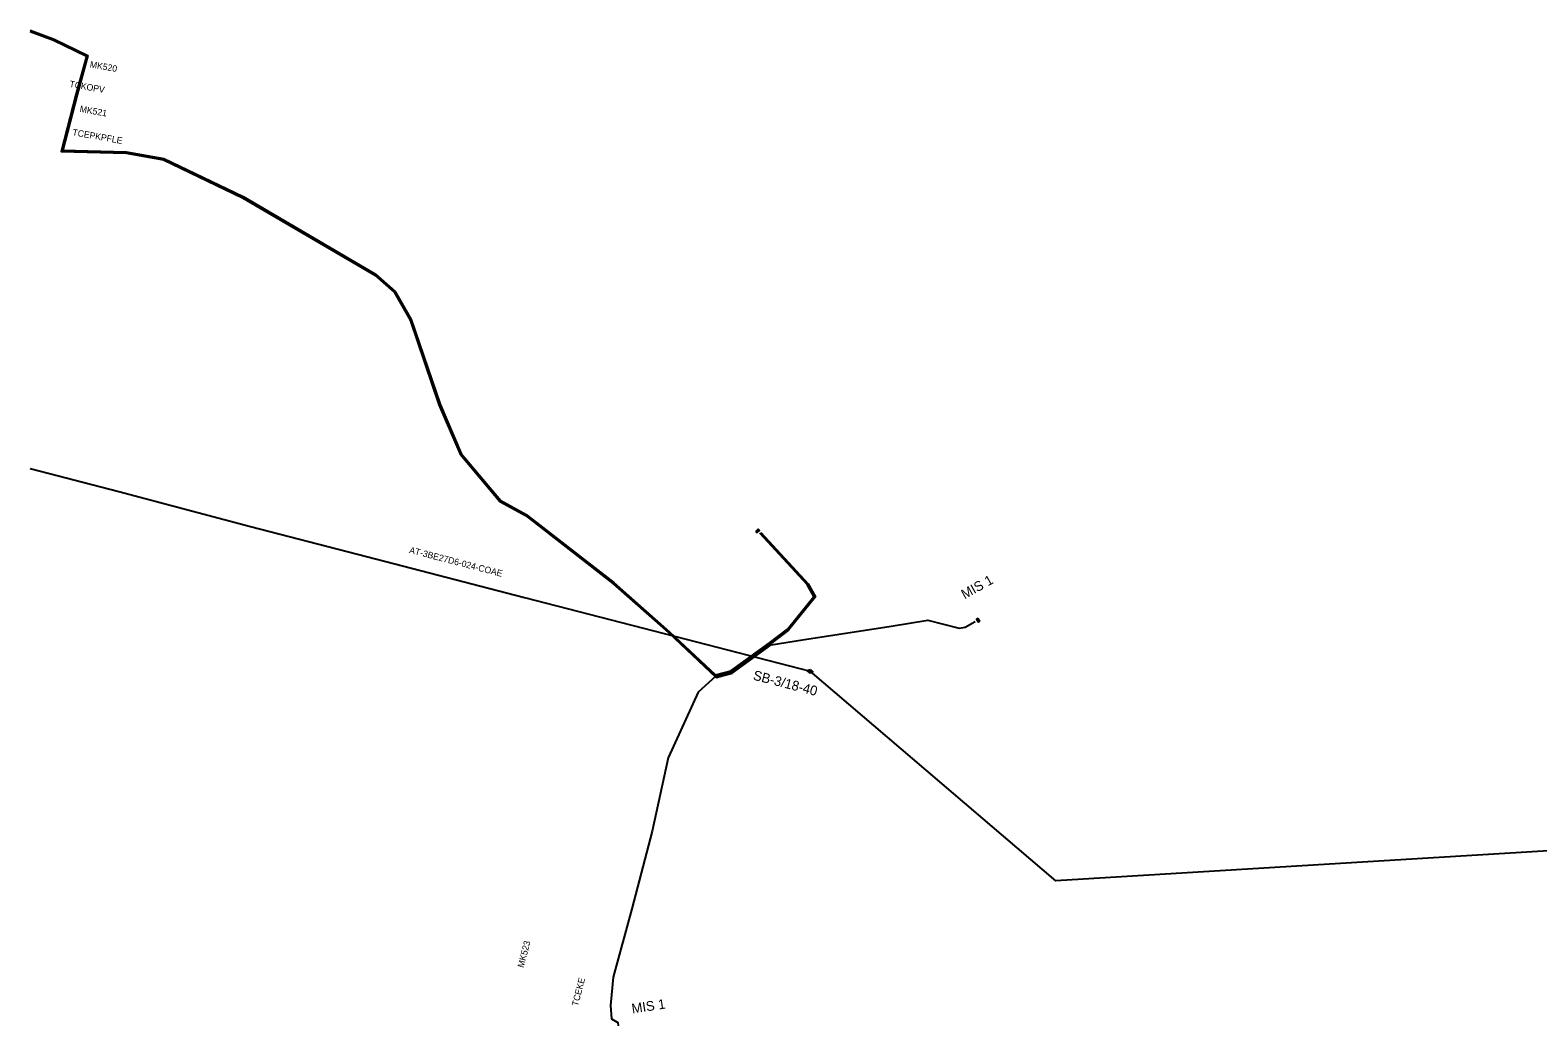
# Model space of a CAD drawing. Extents: x -762501 to -761573, y -1153000 to -1152000.
# Drawn here: x -762500 to -762268.5, y -1152869 to -1152715.9 of the extents above; entities that cross this region are included whole.
import ezdxf

# ---------------------------------------------------------------- set-up
doc = ezdxf.new("R2010")
doc.units = 0
for name, color, linetype in [('Vrstva 1', 7, 'Continuous'), ('Vrstva 10', 7, 'Continuous'), ('Vrstva 2', 7, 'Continuous'), ('Vrstva 9', 7, 'Continuous')]:
    doc.layers.add(name, color=color, linetype=linetype)

msp = doc.modelspace()

# ---------------------------------------------------------------- linework, layer by layer
at = {"layer": 'Vrstva 1'}
for points in [[(-762500, -1152783.22), (-762486.41, -1152786.73), (-762466.18, -1152792.12), (-762445.37, -1152797.51), (-762424.09, -1152803.02), (-762396.1, -1152810.24), (-762380.24, -1152814.37)], [(-761622.14, -1153000), (-761645.21, -1152899.52), (-761677.94, -1152853.03), (-761709.62, -1152807.98), (-762342.52, -1152846.53), (-762380.24, -1152814.37)], [(-762380.755, -1152814.237), (-762380.213, -1152814.113)], [(-762380.755, -1152814.237), (-762380.327, -1152814.604)], [(-762380.327, -1152814.604), (-762379.785, -1152814.479)], [(-762380.213, -1152814.113), (-762379.785, -1152814.479)]]:
    msp.add_lwpolyline(points, dxfattribs=at)
at = {"layer": 'Vrstva 9'}
for p, q in [((-762388.548, -1152792.888), (-762388.216, -1152792.579)), ((-762388.544, -1152792.892), (-762388.213, -1152792.583)), ((-762388.541, -1152792.895), (-762388.21, -1152792.586)), ((-762388.538, -1152792.899), (-762388.206, -1152792.59)), ((-762388.534, -1152792.903), (-762388.203, -1152792.594)), ((-762388.531, -1152792.906), (-762388.199, -1152792.597)), ((-762388.527, -1152792.91), (-762388.196, -1152792.601)), ((-762388.524, -1152792.914), (-762388.193, -1152792.605)), ((-762388.521, -1152792.917), (-762388.189, -1152792.608)), ((-762388.517, -1152792.921), (-762388.186, -1152792.612)), ((-762388.514, -1152792.924), (-762388.182, -1152792.616)), ((-762388.51, -1152792.928), (-762388.179, -1152792.619)), ((-762388.507, -1152792.932), (-762388.176, -1152792.623)), ((-762388.503, -1152792.935), (-762388.172, -1152792.626)), ((-762388.5, -1152792.939), (-762388.169, -1152792.63)), ((-762388.497, -1152792.943), (-762388.165, -1152792.634)), ((-762388.493, -1152792.946), (-762388.162, -1152792.637)), ((-762388.49, -1152792.95), (-762388.159, -1152792.641)), ((-762388.486, -1152792.954), (-762388.155, -1152792.645)), ((-762388.483, -1152792.957), (-762388.152, -1152792.648)), ((-762388.48, -1152792.961), (-762388.148, -1152792.652)), ((-762388.476, -1152792.965), (-762388.145, -1152792.656)), ((-762388.473, -1152792.968), (-762388.141, -1152792.659)), ((-762388.469, -1152792.972), (-762388.138, -1152792.663)), ((-762388.466, -1152792.976), (-762388.135, -1152792.667)), ((-762388.463, -1152792.979), (-762388.131, -1152792.67)), ((-762388.459, -1152792.983), (-762388.128, -1152792.674)), ((-762388.456, -1152792.987), (-762388.124, -1152792.678)), ((-762388.452, -1152792.99), (-762388.121, -1152792.681)), ((-762388.449, -1152792.994), (-762388.118, -1152792.685)), ((-762388.446, -1152792.998), (-762388.114, -1152792.689)), ((-762388.442, -1152793.001), (-762388.111, -1152792.692)), ((-762388.439, -1152793.005), (-762388.107, -1152792.696)), ((-762388.435, -1152793.009), (-762388.104, -1152792.7)), ((-762388.432, -1152793.012), (-762388.101, -1152792.703)), ((-762388.428, -1152793.016), (-762388.097, -1152792.707)), ((-762388.425, -1152793.02), (-762388.094, -1152792.711)), ((-762388.422, -1152793.023), (-762388.09, -1152792.714)), ((-762388.418, -1152793.027), (-762388.087, -1152792.718)), ((-762388.415, -1152793.031), (-762388.083, -1152792.722)), ((-762354.663, -1152806.355), (-762354.437, -1152806.748)), ((-762354.659, -1152806.353), (-762354.433, -1152806.745)), ((-762354.655, -1152806.35), (-762354.428, -1152806.743)), ((-762354.65, -1152806.348), (-762354.424, -1152806.74)), ((-762354.646, -1152806.345), (-762354.42, -1152806.738)), ((-762354.642, -1152806.343), (-762354.415, -1152806.735)), ((-762354.637, -1152806.34), (-762354.411, -1152806.733)), ((-762354.633, -1152806.338), (-762354.407, -1152806.73)), ((-762354.629, -1152806.335), (-762354.402, -1152806.728)), ((-762354.624, -1152806.333), (-762354.398, -1152806.725)), ((-762354.62, -1152806.33), (-762354.394, -1152806.723)), ((-762354.616, -1152806.328), (-762354.389, -1152806.72)), ((-762354.611, -1152806.325), (-762354.385, -1152806.718)), ((-762354.607, -1152806.323), (-762354.381, -1152806.715)), ((-762354.603, -1152806.32), (-762354.376, -1152806.713)), ((-762354.598, -1152806.318), (-762354.372, -1152806.71)), ((-762354.594, -1152806.315), (-762354.368, -1152806.708)), ((-762354.59, -1152806.313), (-762354.363, -1152806.705)), ((-762354.586, -1152806.31), (-762354.359, -1152806.703)), ((-762354.581, -1152806.308), (-762354.355, -1152806.7)), ((-762354.577, -1152806.305), (-762354.35, -1152806.698)), ((-762354.573, -1152806.303), (-762354.346, -1152806.695)), ((-762354.568, -1152806.3), (-762354.342, -1152806.693)), ((-762354.564, -1152806.298), (-762354.337, -1152806.69)), ((-762354.56, -1152806.295), (-762354.333, -1152806.688)), ((-762354.555, -1152806.293), (-762354.329, -1152806.685)), ((-762354.551, -1152806.29), (-762354.324, -1152806.683)), ((-762354.547, -1152806.288), (-762354.32, -1152806.68)), ((-762354.542, -1152806.285), (-762354.316, -1152806.678)), ((-762354.538, -1152806.283), (-762354.311, -1152806.675)), ((-762354.534, -1152806.28), (-762354.307, -1152806.673)), ((-762354.529, -1152806.278), (-762354.303, -1152806.67)), ((-762354.525, -1152806.275), (-762354.298, -1152806.668)), ((-762354.521, -1152806.273), (-762354.294, -1152806.665)), ((-762354.516, -1152806.27), (-762354.29, -1152806.663)), ((-762354.512, -1152806.268), (-762354.285, -1152806.66)), ((-762354.508, -1152806.265), (-762354.281, -1152806.658)), ((-762354.503, -1152806.263), (-762354.277, -1152806.655)), ((-762354.499, -1152806.26), (-762354.272, -1152806.653)), ((-762354.495, -1152806.258), (-762354.268, -1152806.65))]:
    msp.add_line(p, q, dxfattribs=at)
for points in [[(-762500, -1152715.88), (-762496.32, -1152717.26), (-762491.12, -1152719.76), (-762492.79, -1152725.83), (-762494.96, -1152734.3), (-762485.26, -1152734.56), (-762479.46, -1152735.58), (-762467.29, -1152741.44), (-762446.96, -1152753.37), (-762443.96, -1152756.02), (-762441.49, -1152760.33), (-762437.06, -1152773.35), (-762433.82, -1152780.93), (-762427.75, -1152788.11), (-762423.84, -1152790.28), (-762410.4, -1152800.7), (-762401.84, -1152808.28), (-762394.76, -1152814.92), (-762392.42, -1152814.27), (-762386.48, -1152809.97), (-762383.71, -1152807.89), (-762379.69, -1152802.9), (-762380.72, -1152801.04), (-762387.98, -1152793.16)], [(-762500, -1152716.1), (-762496.4, -1152717.44), (-762491.36, -1152719.86), (-762492.99, -1152725.77), (-762495.22, -1152734.5), (-762485.28, -1152734.76), (-762479.52, -1152735.78), (-762467.39, -1152741.62), (-762447.08, -1152753.53), (-762444.12, -1152756.14), (-762441.67, -1152760.41), (-762437.24, -1152773.43), (-762434, -1152781.03), (-762427.89, -1152788.27), (-762423.96, -1152790.44), (-762410.52, -1152800.86), (-762401.98, -1152808.42), (-762394.66, -1152815.3), (-762392.24, -1152814.63), (-762386.24, -1152810.29), (-762381.4, -1152809.54), (-762367.79, -1152807.42), (-762362.18, -1152806.5), (-762357.39, -1152807.73), (-762356.44, -1152807.6), (-762354.9, -1152806.74)], [(-762388.551, -1152792.885), (-762388.412, -1152793.033)], [(-762387.83, -1152793.03), (-762380.56, -1152800.92), (-762379.45, -1152802.92), (-762383.57, -1152808.03), (-762386.36, -1152810.13), (-762392.33, -1152814.45), (-762394.73, -1152815.12), (-762397.45, -1152817.58), (-762402.03, -1152827.65), (-762404.53, -1152838.91), (-762407.62, -1152850.83), (-762410.48, -1152861.33), (-762410.88, -1152865.71), (-762410.75, -1152867.73), (-762409.79, -1152868.29), (-762409.71, -1152868.82)], [(-762354.491, -1152806.256), (-762354.666, -1152806.357)]]:
    msp.add_lwpolyline(points, dxfattribs=at)
for points in [[(-762388.584, -1152792.884), (-762388.414, -1152793.066), (-762388.048, -1152792.725), (-762388.218, -1152792.543)], [(-762388.551, -1152792.885), (-762388.219, -1152792.576), (-762388.081, -1152792.724), (-762388.413, -1152793.033)], [(-762354.482, -1152806.223), (-762354.699, -1152806.348), (-762354.449, -1152806.781), (-762354.232, -1152806.656)], [(-762354.491, -1152806.256), (-762354.264, -1152806.648), (-762354.44, -1152806.749), (-762354.666, -1152806.357)]]:
    msp.add_lwpolyline(points, close=True, dxfattribs=at)

# ---------------------------------------------------------------- texts
at = {"layer": 'Vrstva 10'}
for s, height, rotation, p in [('MK520', 0.9943, 349.9892, (-762490.89, -1152721.59)), ('TCKOPV', 0.9943, 349.9892, (-762494.03, -1152724.6)), ('MK521', 0.9943, 349.99486, (-762492.45, -1152728.43)), ('TCEPKPFLE', 0.9943, 349.99486, (-762493.57, -1152732.02)), ('MIS 1', 1.4914, 29.18081, (-762356.54, -1152803.32)), ('MK523', 0.9943, 75.46721, (-762424.24, -1152859.97)), ('TCEKE', 0.9943, 75.46721, (-762415.9, -1152865.87)), ('MIS 1', 1.4914, 8.58362, (-762407.54, -1152866.93))]:
    msp.add_text(s, height=height, rotation=rotation, dxfattribs=at).set_placement(p)
at = {"layer": 'Vrstva 2'}
for s, height, rotation, p in [('AT-3BE27D6-024-COAE', 0.99428, 345.4719, (-762441.87, -1152796.17)), (' SB-3/18-40', 1.49143, 345.40853, (-762389.66, -1152815.48))]:
    msp.add_text(s, height=height, rotation=rotation, dxfattribs=at).set_placement(p)

doc.saveas('drawing.dxf')
